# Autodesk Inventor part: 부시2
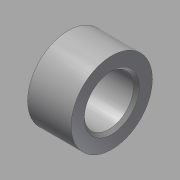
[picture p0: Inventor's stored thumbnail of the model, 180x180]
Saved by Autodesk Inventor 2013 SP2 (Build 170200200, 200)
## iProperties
Created: 2015-09
Part Number: 부시2
Material: 강철, 연강
Document SubType Name: Modeling
Designer: mduedu
Density: 7.86 g/cm^3
Description: 외주 가공
Mass: 45.4 g
Surface Area: 28.3815 cm^2
Volume: 5.77608 cm^3
Author: mduedu
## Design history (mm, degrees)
sketch "스케치1"
  geometry: C1 r 14 at (0, 0); C2 r 8.5 at (0, 0); 1 further point
  constraints: 2 centre point, 2 coincident
  dimensions: "d0" = 28 diameter of C1; "d2" = 17 diameter of C2
extrude "돌출1" new body sketch "스케치1" distance "d3" = 15; taper "d4" = 0 deg
chamfer "모따기1" distance "d5" = 1; stored, may be unused: second distance "d6" = 2, angle "d7" = 45 deg
node "솔리드1"
